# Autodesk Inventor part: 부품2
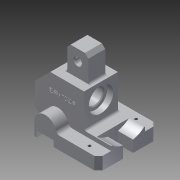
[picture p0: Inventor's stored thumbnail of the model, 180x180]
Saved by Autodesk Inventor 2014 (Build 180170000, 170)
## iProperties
Created: 2016-11
Part Number: 부품2
Material: 알루미늄 6061
Document SubType Name: Modeling
Designer: net
Density: 2.71 g/cm^3
Appearance: 알루미늄 - 평지
Mass: 462.905 g
Surface Area: 317.29 cm^2
Volume: 170.814 cm^3
Author: net
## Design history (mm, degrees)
sketch "스케치1"
  geometry: L1 (31, 18)-(-9, 18); L2 (-9, 18)-(-27, 0); L3 (-27, 0)-(-27, -30); L4 (-27, -30)-(31, -30); L5 (31, -30)-(31, 18); L6 (31, -10)-(31, -30); L7 (63, -22)-(31, -22); L8 (31, -22)-(31, -42); L9 (31, -42)-(63, -42); L10 (63, -42)-(63, -22); 1 further point
  constraints: 20 end point, 3 parallel, 3 perpendicular, 2 horizontal, 1 point on line
  dimensions: "d0" = 45 deg angle of L1 L2; "d1" = 30 distance from line of L4 point (0, 0); "d2" = 48 distance of L4.end L1.start; "d3" = 58 distance of L3.end L4.end; "d4" = 27 distance from line of point (0, 0) L3; "d5" = 18 horizontal distance of L1.end L2.end; "d31" = 42 distance from line of L9 point (0, 0); "d32" = 90 distance between parallel lines of L3 L10; "d33" = 20 distance of L9.end L7.start
extrude "돌출1" new body sketch "스케치1" stored distance "d6" = 40; taper "d7" = 0 deg
sketch "스케치2"
  geometry: L1 (-13, -27)-(-13, -42); L2 (-13, -42)-(-10, -42); L3 (-10, -42)-(-10, -35); L4 (-10, -35)-(10, -35); L5 (10, -35)-(10, -42); L6 (10, -42)-(63, -42); L7 (63, -42)-(63, -27); L8 (63, -27)-(17.292, -27); A1 r 13 centre (0, -27) between (12.488, -23.389) and (-13, -27); A2 r 5 centre (17.292, -22) between (12.488, -23.389) and (17.292, -27); 1 further point
  constraints: 16 end point, 5 parallel, 4 point on circle, 3 perpendicular, 3 tangent, 2 centre point, 1 horizontal alignment, 1 vertical, 1 vertical alignment
  dimensions: "d8" = 5 radius of A2; "d9" = 20 distance of L3.end L4.end; "d10" = 3 distance of L1.end L2.end; "d11" = 7 distance of L2.end L3.end; "d12" = 13 radius of A1; "d13" = 15 distance between parallel lines of L6 L8; "d14" = 63 distance from line of L7 A1.centre; "d15" = 42 distance from line of point (0, 0) L6
extrude "돌출2" join sketch "스케치2" stored distance "d16" = 70; taper "d17" = 0 deg
sketch "스케치3"
  geometry: L1 (63, -22)-(63, -42) reference; L2 (63, -42)-(10, -42) reference; L3 (10, -42)-(10, -35) reference; L4 (10, -35)-(-10, -35) reference; L5 (-10, -35)-(-10, -42) reference; L6 (-10, -42)-(-13, -42) reference; L7 (-13, -42)-(-13, -30) reference; L8 (-13, -30)-(-27, -30) reference; L9 (-27, -30)-(-27, 0) reference; L10 (-27, 0)-(-9, 18) reference; L11 (-9, 18)-(31, 18) reference; L12 (31, 18)-(31, -22) reference; L13 (1, 18)-(1, 44); L14 (1, 44)-(5, 48); L15 (5, 48)-(22, 48); L16 (22, 48)-(26, 44); L17 (26, 44)-(26, 18); L18 (31, -22)-(63, -22) reference; 1 further point
  constraints: 10 end point, 3 perpendicular, 2 point on line, 1 parallel
  dimensions: "d18" = 4 horizontal distance of L13.end L14.end; "d19" = 4 horizontal distance of L15.end L16.end; "d20" = 4 horizontal distance of L13.end L14.end; "d21" = 25 distance between parallel lines of L17 L13; "d22" = 5 distance between parallel lines of L17 L12; "d23" = 90 distance between parallel lines of L2 L15
extrude "돌출3" join sketch "스케치3" stored distance "d24" = 20; taper "d25" = 0 deg
sketch "스케치5"
  geometry: L1 (0, 0)-(40, 0) reference; L2 (55, -20)-(-15, -20) reference; L3 (14, -6.373)-(14, -20); L4 (26, -6.373)-(26, -20); A1 r 29 centre (20, 22) between (1.106, 0) and (14, -6.373); A2 r 29 centre (20, 22) between (26, -6.373) and (38.894, 0); 1 further point
  constraints: 4 end point, 4 point on circle, 4 point on line, 2 centre point, 2 perpendicular, 1 coincident
  dimensions: "d35" = 12 distance between parallel lines of L3 L4; "d36" = 6 distance from line of point (20, 22) L3; "d37" = 29 radius of A1; "d38" = 29 radius of A2
extrude "돌출4" cut sketch "스케치5" distance "d39" = 18; taper "d40" = 0 deg
sketch "스케치6"
  geometry: 1 further point
hole "구멍1" sketch "스케치6" at (-20, 22) diameter "d41" = 20; stored, may be unused: countersink angle "d45" = 90 deg, drill point angle "d47" = 118 deg; dims "d42" = 6, "d43" = 29, "d44" = 7, "d46" = 8
sketch "스케치7"
  geometry: L1 (1, 44)-(1, 18) reference; 2 further points
  dimensions: "d48" = 12.5 distance from line of point (13.5, 35) L1; "d49" = 35 vertical distance of point (0, 0) point (13.5, 35)
hole "구멍2" sketch "스케치7" at (13.5, 35) diameter "d50" = 8; stored, may be unused: countersink angle "d54" = 90 deg, drill point angle "d56" = 118 deg; dims "d51" = 6, "d52" = 29, "d53" = 7, "d55" = 8
chamfer "모따기1" distance "d57" = 4; stored, may be unused: second distance "d58" = 2, angle "d59" = 45 deg
chamfer "모따기2" distance "d60" = 1; stored, may be unused: second distance "d61" = 2, angle "d62" = 45 deg
chamfer "모따기3" distance "d63" = 5; stored, may be unused: second distance "d64" = 2, angle "d65" = 45 deg
sketch "스케치8"
  geometry: L1 (45.708, -10)-(45.708, 0) reference; 3 further points
  constraints: 1 vertical alignment
  dimensions: "d66" = 55 distance of point (27.708, -7.5) point (27.708, 47.5); "d67" = 27.5 vertical distance of point (-17.292, 20) point (27.708, 47.5); "d68" = 18 distance from line of L1 point (27.708, -7.5)
hole "구멍3" sketch "스케치8" at (27.708, -7.5), (27.708, 47.5) diameter "d69" = 3.242; stored, may be unused: countersink angle "d73" = 90 deg, drill point angle "d75" = 118 deg; dims "d70" = 20, "d71" = 29, "d72" = 7, "d74" = 8
fillet "모깎기1" dims "d76" = 3
sketch "스케치9"
  geometry: L1 (31, -19)-(31, 18) reference; L2 (31, 18)-(-9, 18) reference; 2 further points
  constraints: 1 other
  dimensions: "d77" = 18 distance from line of L2 point (6, 0); "d78" = 25 distance from line of point (6, 0) L1
feature "엠보싱1" sketch "스케치9" dims "d0" = 45 deg, "d1" = 30, "d2" = 48, "d3" = 58, "d4" = 27, "d5" = 18, "d31" = 42, "d32" = 90, "d33" = 20, "d79" = 0.5, "d80" = 0
node "솔리드1"
node "절단 모서리 투영1"
other parameters: "d34" = 58
